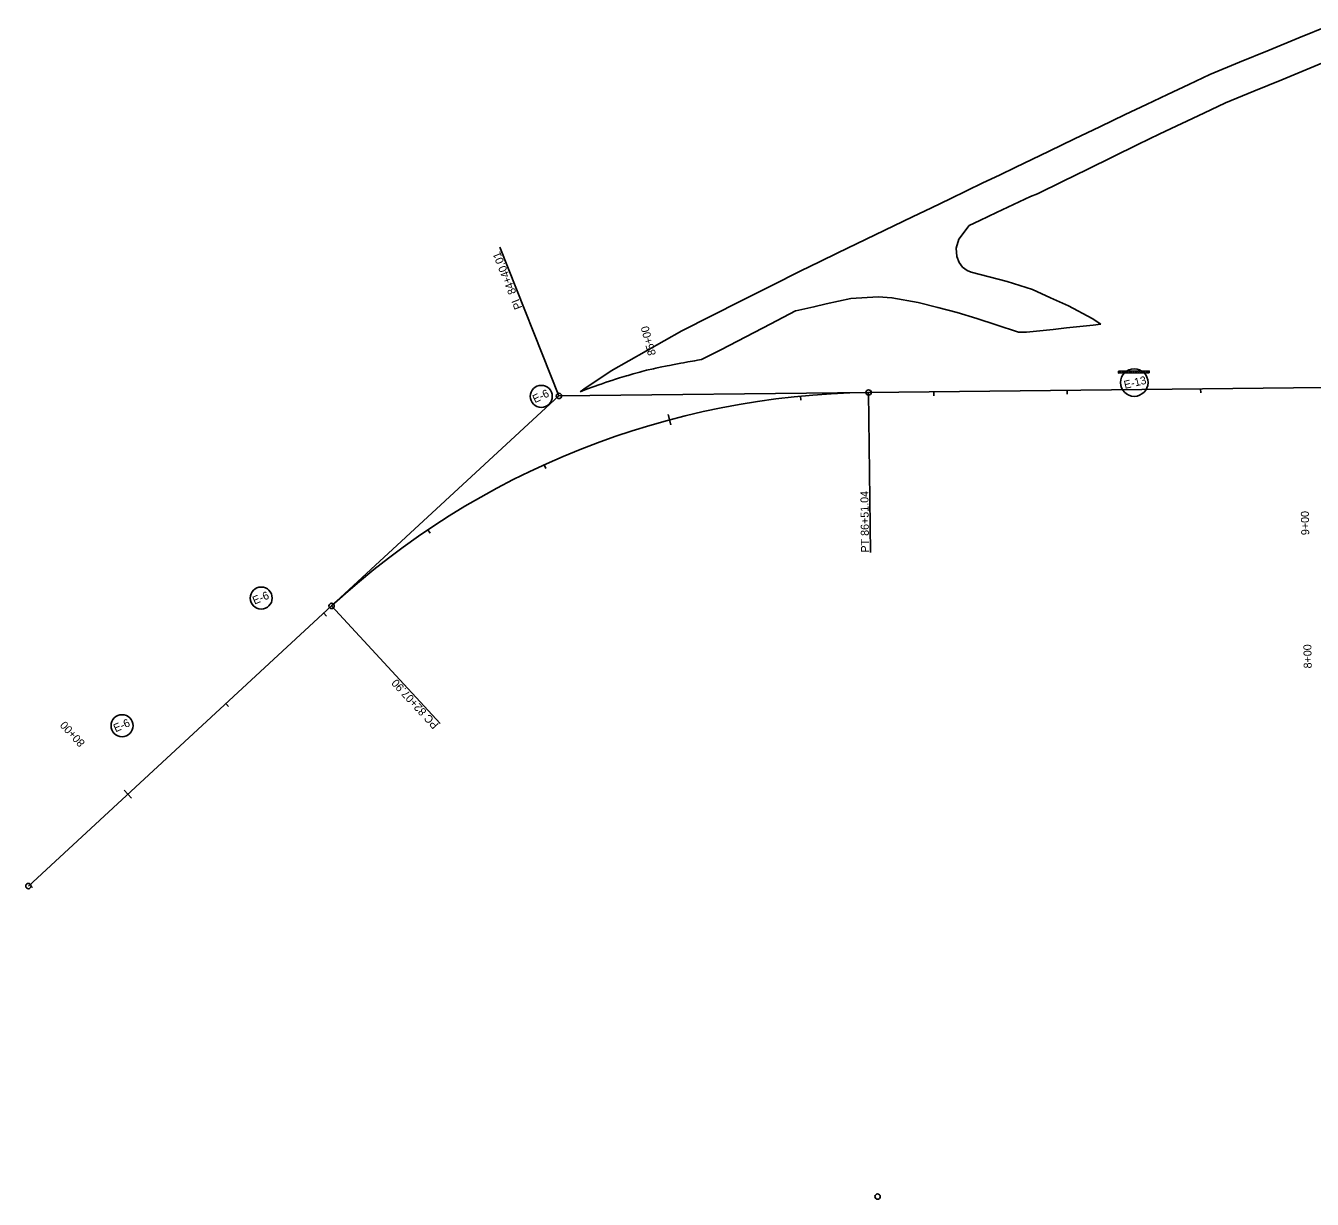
# Model space of a CAD drawing. Extents: x 1710760 to 1712722, y 548603 to 551099.
# Drawn here: x 1710760 to 1711724, y 548603 to 549484 of the extents above; entities that cross this region are included whole.
import ezdxf

# ---------------------------------------------------------------- set-up
doc = ezdxf.new("R2010")
doc.units = 0
for name, color, linetype in [('R_Draft', 7, 'Continuous'), ('R_Erosion', 7, 'Continuous'), ('R_Erosion_STG 2', 7, 'Continuous'), ('R_Horz Alg', 7, 'Continuous'), ('R_Horz Alg Annot', 7, 'Continuous')]:
    doc.layers.add(name, color=color, linetype=linetype)

msp = doc.modelspace()

# ---------------------------------------------------------------- linework, layer by layer
at = {"layer": 'R_Draft'}
for points in [[(1711175.54, 549209.1), (1711178.24, 549210.91), (1711198.89, 549224.81), (1711212.12, 549232.3), (1711225.36, 549239.79), (1711238.6, 549247.28), (1711251.83, 549254.77), (1711274.11, 549266.02), (1711296.38, 549277.27), (1711318.65, 549288.53), (1711340.93, 549299.78), (1711354.88, 549306.5), (1711368.83, 549313.23), (1711382.78, 549319.95), (1711396.74, 549326.67), (1711410.78, 549333.47), (1711424.82, 549340.27), (1711438.86, 549347.07), (1711452.9, 549353.87), (1711465.23, 549359.77), (1711477.55, 549365.67), (1711489.88, 549371.57), (1711502.21, 549377.46), (1711508.01, 549380.23), (1711527.06, 549389.44), (1711546.11, 549398.65), (1711565.15, 549407.86), (1711584.2, 549417.07), (1711600.08, 549424.58), (1711615.96, 549432.09), (1711631.83, 549439.59), (1711647.71, 549447.1), (1711669.9, 549456.22), (1711692.1, 549465.34), (1711714.29, 549474.46), (1711736.48, 549483.57)], [(1711743.58, 549460.51), (1711722.54, 549451.81), (1711701.51, 549443.1), (1711680.47, 549434.39), (1711659.43, 549425.69), (1711643, 549417.91), (1711626.58, 549410.14), (1711610.15, 549402.37), (1711593.72, 549394.59), (1711574.9, 549385.33), (1711556.07, 549376.06), (1711537.25, 549366.79), (1711518.42, 549357.53), (1711513.11, 549355.58), (1711500.43, 549349.53), (1711487.76, 549343.48), (1711475.08, 549337.43), (1711467.16, 549333.64)], [(1711467.16, 549333.64), (1711459.43, 549323.47), (1711457.39, 549316.84), (1711457.87, 549310.57), (1711459.56, 549306.05), (1711462.1, 549302.61), (1711465.76, 549299.93), (1711468.68, 549298.75), (1711482.21, 549295.23), (1711495.74, 549291.71), (1711514.68, 549285.73), (1711528.22, 549279.62), (1711541.75, 549273.5), (1711559.3, 549263.97), (1711565.96, 549259.72)], [(1711504.26, 549253.63), (1711487.49, 549259.36), (1711472.88, 549263.98), (1711458.27, 549268.6), (1711443.66, 549272.29), (1711429.05, 549275.98), (1711409.26, 549279.62), (1711398.86, 549280.13), (1711378.37, 549278.89), (1711360, 549274.98), (1711350.83, 549272.67), (1711337.31, 549269.83)], [(1711337.31, 549269.83), (1711337.1, 549269.7), (1711318.38, 549260), (1711299.66, 549250.3), (1711280.94, 549240.61), (1711266.56, 549233.16)], [(1711565.96, 549259.72), (1711560.17, 549259.06), (1711550.19, 549257.98), (1711540.2, 549256.9), (1711530.21, 549255.87), (1711520.22, 549254.84), (1711510.23, 549253.84), (1711504.26, 549253.63)], [(1711266.56, 549233.16), (1711263.6, 549232.67), (1711261.44, 549232.3), (1711256.27, 549231.41), (1711253.1, 549230.84), (1711251.11, 549230.47), (1711245.95, 549229.49), (1711242.63, 549228.84), (1711240.8, 549228.48), (1711235.65, 549227.41), (1711232.18, 549226.66), (1711230.52, 549226.29), (1711225.39, 549225.14), (1711221.78, 549224.27), (1711220.29, 549223.85), (1711215.24, 549222.41), (1711211.52, 549221.33), (1711210.2, 549220.93), (1711205.16, 549219.43), (1711201.3, 549218.23), (1711200.15, 549217.84), (1711195.17, 549216.16), (1711191.2, 549214.79), (1711190.21, 549214.44), (1711185.25, 549212.68), (1711181.15, 549211.19), (1711180.32, 549210.88), (1711175.54, 549209.1)]]:
    msp.add_lwpolyline(points, dxfattribs=at)
at = {"layer": 'R_Erosion'}
for p, q in [((1711602.06, 549224.83), (1711579.06, 549224.57)), ((1711579.07, 549223.82), (1711579.81, 549224.58)), ((1711579.74, 549223.08), (1711581.23, 549224.6)), ((1711581.16, 549223.1), (1711582.64, 549224.61)), ((1711582.57, 549223.11), (1711584.05, 549224.63)), ((1711583.99, 549223.13), (1711585.47, 549224.65)), ((1711585.4, 549223.14), (1711586.88, 549224.66)), ((1711586.81, 549223.16), (1711588.3, 549224.68)), ((1711588.23, 549223.18), (1711589.71, 549224.69)), ((1711589.64, 549223.19), (1711591.12, 549224.71)), ((1711591.06, 549223.21), (1711592.54, 549224.73)), ((1711592.47, 549223.23), (1711593.95, 549224.74)), ((1711593.88, 549223.24), (1711595.37, 549224.76)), ((1711595.3, 549223.26), (1711596.78, 549224.77)), ((1711596.71, 549223.27), (1711598.2, 549224.79)), ((1711598.13, 549223.29), (1711599.61, 549224.81)), ((1711599.54, 549223.31), (1711601.02, 549224.82)), ((1711600.96, 549223.32), (1711602.06, 549224.46))]:
    msp.add_line(p, q, dxfattribs=at)
msp.add_lwpolyline([(1711579.06, 549224.57), (1711579.08, 549223.07), (1711602.08, 549223.33), (1711602.06, 549224.83)], dxfattribs=at)
for centre in [(1711146.4, 549205.6), (1710936.46, 549054.3), (1710832.2, 548958.62)]:
    msp.add_circle(centre, 8.26, dxfattribs=at)
at = {"layer": 'R_Erosion_STG 2'}
msp.add_circle((1711590.95, 549215.94), 10.32, dxfattribs=at)
at = {"layer": 'R_Horz Alg'}
for p, q in [((1711391.77, 549208.53), (1711733, 549212.35)), ((1710761.95, 548838.38), (1710989.21, 549048.39))]:
    msp.add_line(p, q, dxfattribs=at)
msp.add_arc((1711398.54, 548605.45), 603.11, 90.64281, 132.74131, dxfattribs=at)
at = {"layer": 'R_Horz Alg Annot'}
for p, q in [((1710989.21, 549048.39), (1711159.68, 549205.92)), ((1711159.68, 549205.92), (1711391.77, 549208.53))]:
    msp.add_line(p, q, dxfattribs=at)
for points in [[(1711159.68, 549205.92), (1711115.32, 549317.42)], [(1711341.11, 549202.81), (1711340.82, 549205.8)], [(1711391.77, 549208.53), (1711393.12, 549088.53)], [(1711440.76, 549206.08), (1711440.73, 549209.07)], [(1711540.75, 549207.2), (1711540.72, 549210.2)], [(1711640.75, 549208.32), (1711640.71, 549211.32)], [(1711241.49, 549191.9), (1711243.56, 549184.17)], [(1711149.75, 549151.57), (1711148.51, 549154.3)], [(1711063.03, 549103.01), (1711061.35, 549105.5)], [(1710985.45, 549040.83), (1710983.41, 549043.03)], [(1710989.21, 549048.39), (1711070.66, 548960.26)], [(1710912, 548972.96), (1710909.97, 548975.16)], [(1710833.81, 548910.23), (1710839.24, 548904.35)], [(1710765.12, 548837.22), (1710763.08, 548839.42)]]:
    msp.add_lwpolyline(points, dxfattribs=at)
for centre in [(1711159.68, 549205.92), (1711391.77, 549208.53), (1710989.21, 549048.39), (1710761.95, 548838.38), (1711398.54, 548605.45)]:
    msp.add_circle(centre, 2, dxfattribs=at)

# ---------------------------------------------------------------- texts
at = {"layer": 'R_Erosion'}
for rotation, p in [(25.17281, (1711141.62, 549200.47)), (22.40034, (1710931.45, 549049.41)), (23.61828, (1710827.29, 548953.63))]:
    msp.add_text('E-6 ', height=5.999, rotation=rotation, dxfattribs=at).set_placement(p)
at = {"layer": 'R_Erosion_STG 2'}
msp.add_text('E-13', height=5.999, rotation=13.5638, dxfattribs=at).set_placement((1711583.96, 549211.17))
at = {"layer": 'R_Horz Alg Annot'}
for s, rotation, p in [('PI  84+40.01', 111.69206, (1711132.24, 549272.19)), ('85+00', 104.99186, (1711232.49, 549237.11)), ('PT 86+51.04', 90.64281, (1711392.12, 549088.52)), ('9+00', 91.07865, (1711722.14, 549101.6)), ('8+00', 91.07865, (1711724.02, 549001.62)), ('PC 82+07.90', 132.74131, (1711069.92, 548959.58)), ('80+00', 132.74131, (1710804.79, 548946.05))]:
    msp.add_text(s, height=6, rotation=rotation, dxfattribs=at).set_placement(p)

doc.saveas('drawing.dxf')
